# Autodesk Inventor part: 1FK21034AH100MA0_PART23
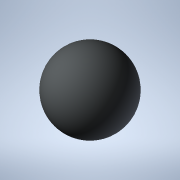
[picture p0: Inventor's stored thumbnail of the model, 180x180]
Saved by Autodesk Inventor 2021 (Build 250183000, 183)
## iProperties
Created: 2025-04
Part Number: 1FK21034AH100MA0_PART23
Material: Generic
Catalog Web Link: www.3dfindit.com
Description: -Servo synchronous motor
Document SubType Name: Modeling
Designer: psAdmin
Mass: 0.113097 g
Surface Area: 1.13097 cm^2
Volume: 0.113097 cm^3
Density: 1 g/cm^3
Appearance: PSOLRGB-212-217-219
Category: PARTsolutions
Title: 1FK21034AH100MA0_PART23
Author: Cadenas PARTsolutions
Comments: Servo synchronous motor
Sending System: PARTsolutions
Preprocessor: ST-DEVELOPER v19.3
PSOL_IDENT_0: {$CADENAS_DATA/23d-libs/siemens_ag/_cat_/39/97/1fk21034ah100ma0.prj},216 {VTYP=3D},{NB=1FK21034AH100
PSOL_IDENT_1: MA0_PART23},{LINA=1FK21034AH100MA0_PART23},{NN=1FK21034AH100MA0_PART23},{NOPRJ=TRUE},{DATE=19.08.202
PSOL_IDENT_2: 5 14:00:33},{GEOMDATE=30.07.2025 02:02:21},{VERSION=},{LINEID=10},{WBVAR=},{WBNUMERIC=}  {NB=1FK2103
PSOL_IDENT_3: 4AH100MA0_PART23},{LINA=1FK21034AH100MA0_PART23},{KT=DUMMY},{PREVIEW=../../../_pool_/d3/78/p_d211_xx
PSOL_IDENT_4: _00934j.png},{DESCSHORT=SIMOTICS S-1FK2 HD, SINAMICS S210 3AC 400V-480V, 1.01 Nm, 4500 rpm},{DESCLON
PSOL_IDENT_5: G=SIMOTICS S-1FK2 HD servo motor M0=1.27 Nm; PN = 0.48 kW at nN=4500 rpm (380-480 V); PN = 0.3 kW at
PSOL_IDENT_6: nN=2500 rpm (200-240 V); with holding brake; degree of protection IP64; cylindrical shaft D14 x 30
PSOL_IDENT_7: mm; absolute encoder 22-bit + 12-bit multiturn (encoder AM22DQC); with OCC interface; plug size M17,
PSOL_IDENT_8: rotatable; SIMOTICS S-1FK2 servomotorfor a wide range of uses in industrial environments. SIMOTICS
PSOL_IDENT_9: S‑1FK2 servomotors are compact synchronous motors with a high dynamic performance that set themselve
PSOL_IDENT_10: s apart as a result of their high power density, degree of protection and overload capability. The m
PSOL_IDENT_11: otors are available in two variants: as High Dynamic variant (highest dynamic performance as a resul
PSOL_IDENT_12: t of the low intrinsic moment of inertia for applications demanding a high dynamic performance with
PSOL_IDENT_13: low moved masses) - and as Compact variant (precise and stable closed-loop control for medium up to
PSOL_IDENT_14: large moved masses as a result of a medium intrinsic moment of inertia). SIMOTICSS‑1FK2 servomotors
PSOL_IDENT_15: fully exploit their strengths in a system with the SINAMICSS210 frequency converter and simple conne
PSOL_IDENT_16: ction using the one cable connection (OCC). Advantages include the short control and positioning tim
PSOL_IDENT_17: es, fast and precise correction of disturbing quantities as well as stable control with a high dynam
PSOL_IDENT_18: ic performance. The servo motors can be configured to address a wide range of requirements. For exam
PSOL_IDENT_19: ple with and without holding brake, IP64 or IP65 degree of protection, singleturn or multiturn absol
PSOL_IDENT_20: ute encoders - to name just a few. Further, the servomotors are available in different shaft heights
PSOL_IDENT_21: extending from 20 to 100. A shaft sealing ring is available to achieve an IP65 degree of protection
PSOL_IDENT_22: and for subsequent mounting at the motor or as spare part. SIMOTICS - the optimum motor for each an
PSOL_IDENT_23: d every motion control application.},{INTNO=195125454019},{SUPPLIERALTNO=1FK2103-4AH10-0MA0},{MANUID=
PSOL_IDENT_24: 1FK21034AH100MA0},{MANUNAME=Siemens},{MANUTYPEDESC=SYNCHRONOUS MOTOR 1FK2 HD 1,27 NM},{AAU732=SIMOTI
PSOL_IDENT_25: CS},{AAO057=S-1FK2},{AAU734=SIMOTICS S-1FK2 HD servo motor M0=1.27 Nm; PN = 0.48 kW at nN=4500 rpm (
PSOL_IDENT_26: 380-480 V); PN = 0.3 kW at nN=2500 rpm (200-240 V); with holding brake; degree of protection IP64; c
PSOL_IDENT_27: ylindrical shaft D14 x 30 mm; absolute encoder 22-bit + 12-bit multiturn (encoder AM22DQC); with OCC
PSOL_IDENT_28: interface; plug size M17, rotatable;},{AAW338=SYNCHRONOUS MOTOR 1FK2 HD 1,27 NM},{AAO742=SIMOTICS},
PSOL_IDENT_29: {AAO663=4034106444921},{NOCUPEROU=1},{PRICEQUANTITY=1},{QUANTITYMIN=1},{QUANTITYINT=1},{CTN=85015100
PSOL_IDENT_30: },{COO=RO},{AAO676=1FK2103-4AH10-0MA0},{AAO677=Siemens AG},{ORDERUNIT=C62},{CONTENTUNIT=C62}
NB: 1FK21034AH100MA0_PART23
NT: Servo synchronous motor
NBSYN: $MANUID._PART23
LINA: 1FK21034AH100MA0_PART23
CATALOG: SIEMENS
PREVIEW: ../../../_pool_/d3/78/p_d211_xx_00934j.png
DESCSHORT: SIMOTICS S-1FK2 HD, SINAMICS S210 3AC 400V-480V, 1.01 Nm, 4500 rpm
DESCLONG: SIMOTICS S-1FK2 HD servo motor M0=1.27 Nm; PN = 0.48 kW at nN=4500 rpm (380-480 V); PN = 0.3 kW at nN=2500 rpm (200-240 V); with holding brake; degree of protec
INTNO: 195125454019
SUPPLIERALTNO: 1FK2103-4AH10-0MA0
MANUID: 1FK21034AH100MA0
MANUNAME: Siemens
MANUTYPEDESC: SYNCHRONOUS MOTOR 1FK2 HD 1,27 NM
AAU732: SIMOTICS
AAO057: S-1FK2
AAU734: SIMOTICS S-1FK2 HD servo motor M0=1.27 Nm; PN = 0.48 kW at nN=4500 rpm (380-480 V); PN = 0.3 kW at nN=2500 rpm (200-240 V); with holding brake; degree of protec
AAW338: SYNCHRONOUS MOTOR 1FK2 HD 1,27 NM
AAO742: SIMOTICS
AAO663: 4034106444921.0
NOCUPEROU: 1
PRICEQUANTITY: 1
QUANTITYMIN: 1
QUANTITYINT: 1
CTN: 85015100
COO: RO
ARTICLENO: 1FK21034AH100MA0_PART23
BOMINFO: 1FK21034AH100MA0_PART23
CREATOR: CADENAS GmbH
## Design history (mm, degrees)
feature "2025_04_17_15_09_00_0361"
body "Solid1"
